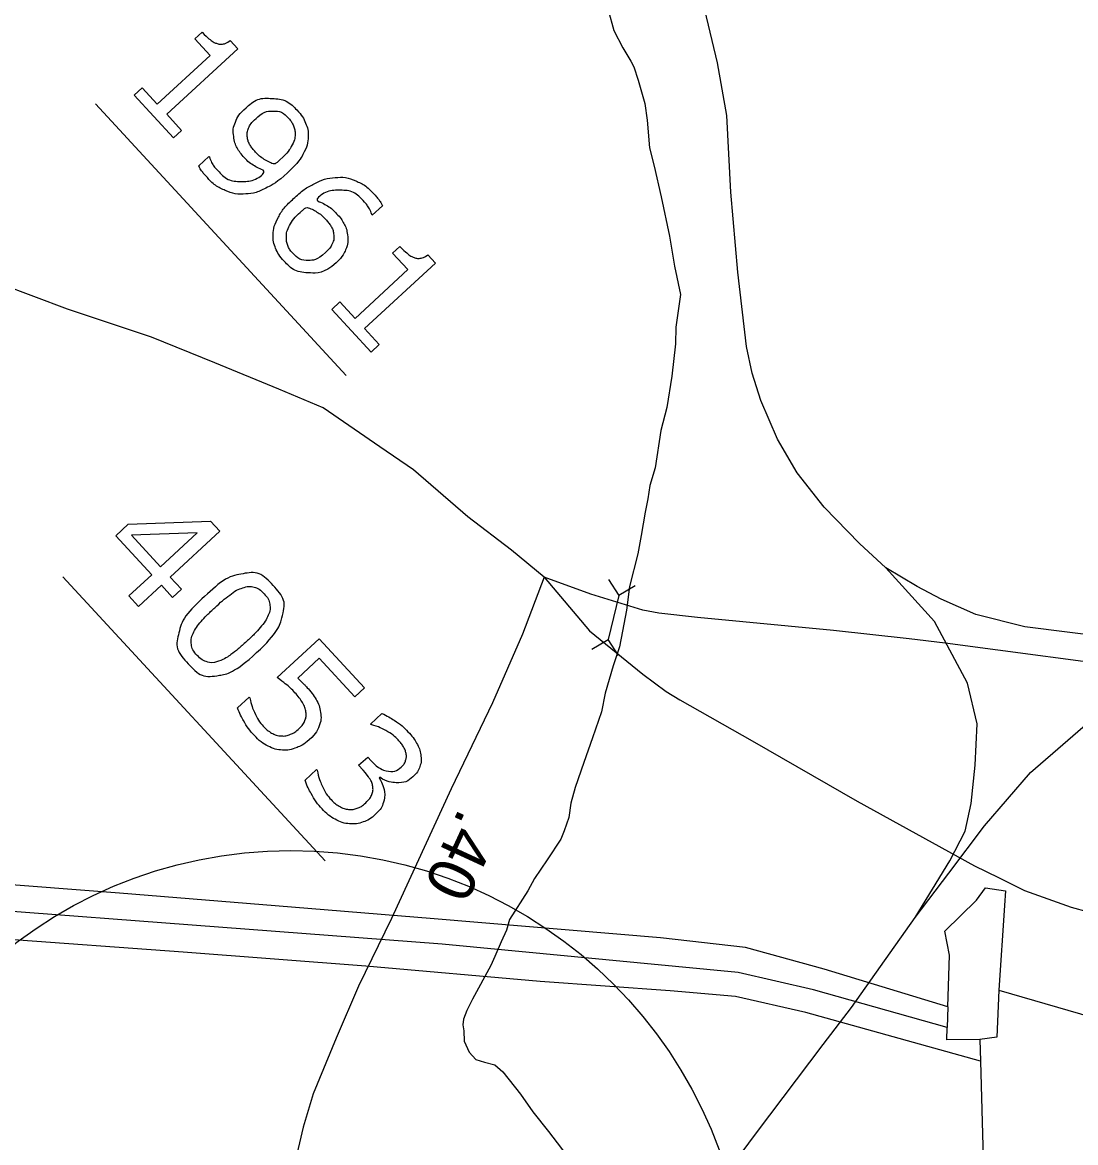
# Model space of a CAD drawing. Extents: x 1695041 to 1706254, y 786537 to 798223.
# Drawn here: x 1703171.6 to 1703301.4, y 796996.4 to 797134.4 of the extents above; entities that cross this region are included whole.
import ezdxf

# ---------------------------------------------------------------- set-up
doc = ezdxf.new("R2010")
doc.units = 0
for name, color, linetype in [('Default', 7, 'Continuous'), ('Old_Level_13', 7, 'Continuous'), ('Old_Level_30', 7, 'Continuous'), ('Old_Level_32', 7, 'Continuous')]:
    doc.layers.add(name, color=color, linetype=linetype)

msp = doc.modelspace()

# ---------------------------------------------------------------- linework, layer by layer
at = {"layer": 'Default'}
for p, q in [((1703180.62, 797124.38), (1703211.51, 797090.92)), ((1703176.62, 797066.11), (1703208.93, 797031.11)), ((1703243.85, 797065.77), (1703245.13, 797063.81)), ((1703247.16, 797064.98), (1703245.13, 797063.81)), ((1703245.13, 797063.81), (1703243.83, 797058.37)), ((1703241.8, 797057.2), (1703243.83, 797058.37)), ((1703245.11, 797056.41), (1703243.83, 797058.37)), ((1703285.68, 797013.13), (1703285.6, 797010.59)), ((1703289.63, 797009.1), (1703289.7, 797006.43))]:
    msp.add_line(p, q, dxfattribs=at)
for points in [[(1703190.25, 797120.18), (1703185.4, 797125.44), (1703186.39, 797126.35), (1703188.25, 797124.33), (1703194.76, 797130.34), (1703192.9, 797132.36), (1703193.78, 797133.18)], [(1703197.23, 797132.16), (1703198.16, 797131.15), (1703189.41, 797123.08), (1703191.24, 797121.1), (1703190.25, 797120.18)], [(1703193.36, 797116.74), (1703194.61, 797117.89), (1703194.67, 797117.83)], [(1703216, 797111.82), (1703214.75, 797110.67), (1703214.69, 797110.73)], [(1703214.61, 797093.79), (1703209.76, 797099.04), (1703210.75, 797099.96), (1703212.62, 797097.94), (1703219.12, 797103.94), (1703217.26, 797105.96), (1703218.15, 797106.78)], [(1703221.59, 797105.77), (1703222.52, 797104.76), (1703213.77, 797096.68), (1703215.6, 797094.7), (1703214.61, 797093.79)], [(1703190.14, 797063.57), (1703188.76, 797065.06), (1703185.94, 797062.45), (1703184.75, 797063.75), (1703187.57, 797066.36), (1703183.13, 797071.16), (1703184.68, 797072.59), (1703194.82, 797072.95), (1703195.97, 797071.71), (1703189.84, 797066.06), (1703191.22, 797064.57), (1703190.14, 797063.57)], [(1703188.65, 797067.35), (1703193.18, 797071.53), (1703185.06, 797071.24), (1703188.65, 797067.35)], [(1703321.31, 797061.94), (1703315.69, 797059.63), (1703313.49, 797058.77), (1703310.57, 797058.37), (1703306.6, 797058.49), (1703295.15, 797059.93), (1703289.13, 797061.46), (1703284.84, 797063.34), (1703281.91, 797064.92), (1703278.04, 797067.22)], [(1703203.04, 797053.69), (1703208.21, 797058.45), (1703213.78, 797052.42), (1703212.6, 797051.33), (1703208.22, 797056.07), (1703205.56, 797053.61)], [(1703285.68, 797013.13), (1703270.43, 797017.78), (1703260.74, 797020.43), (1703250.27, 797021.64), (1703222.38, 797023.95), (1703204.79, 797025.42), (1703183.61, 797027.12), (1703167.05, 797028.4), (1703150.24, 797029.69), (1703133.54, 797030.98), (1703124.57, 797031.78), (1703115.7, 797032.57), (1703115.06, 797037.11), (1703118.33, 797044.24), (1703122.27, 797051.58)], [(1703198.15, 797049.98), (1703199.57, 797051.29), (1703199.66, 797051.19)], [(1703285.6, 797010.59), (1703269.14, 797015.21), (1703259.82, 797017.34), (1703223.36, 797020.86), (1703137.92, 797027.32), (1703108.37, 797031.02), (1703096.16, 797034.26), (1703081.92, 797034.91), (1703062.04, 797036.28), (1703040.38, 797037.67), (1703020.02, 797038.85), (1703002.94, 797039.89), (1702982.67, 797041.42), (1702965.31, 797042.47), (1702957.75, 797042.96), (1702953.78, 797043.59), (1702935.24, 797047.06), (1702923.39, 797049.63), (1702900.08, 797048.94)], [(1703214.57, 797047.9), (1703214.51, 797047.97), (1703215.91, 797049.27)], [(1703289.7, 797006.43), (1703268.17, 797012.44), (1703259.5, 797014.41), (1703251.47, 797015.1), (1703235.43, 797016.24), (1703213.94, 797018.14), (1703191.44, 797019.88), (1703168.84, 797021.51), (1703144.25, 797023.35), (1703122.49, 797025.14), (1703108.81, 797026.43), (1703095.3, 797030.24), (1703081.37, 797031.4), (1703060.9, 797032.87), (1703035.99, 797034.53), (1703015.51, 797035.99), (1702993.46, 797037.4), (1702976.12, 797038.31), (1702961.7, 797039.29), (1702953.95, 797040.12), (1702935.07, 797043.53), (1702923.94, 797045.61), (1702903.01, 797045.39)], [(1703213.62, 797042.27), (1703213.06, 797042.88), (1703214.18, 797043.9), (1703214.61, 797043.43)], [(1703206.46, 797041.07), (1703207.86, 797042.37), (1703207.96, 797042.27)], [(1703215.69, 797041.41), (1703215.6, 797041.33)], [(1703285.68, 797013.13), (1703285.86, 797019.5), (1703285.3, 797022.44), (1703289.2, 797026.27), (1703290.32, 797027.78), (1703292.79, 797027.4), (1703292.65, 797025.63), (1703291.97, 797015.19)], [(1703291.97, 797015.19), (1703291.73, 797009.38), (1703289.63, 797009.1)], [(1703291.97, 797015.19), (1703324.69, 797005.69), (1703340.9, 797002.01), (1703346.94, 797000.11), (1703357.14, 796996.22), (1703368.85, 796991.59), (1703392.4, 796995.22), (1703415.7, 797000.36), (1703437.39, 797006.05), (1703475.08, 797015.18), (1703510.21, 797012.82), (1703534.98, 797011.35), (1703569.35, 797009.42), (1703597.22, 797007.38), (1703614.23, 797006.26), (1703657.83, 797003.31), (1703684.12, 797001.47)], [(1703289.63, 797009.1), (1703285.56, 797009.05), (1703285.6, 797010.59)], [(1703289.7, 797006.43), (1703290.17, 796989.97), (1703290.72, 796977.07), (1703307.24, 796958.38), (1703315.35, 796958.33), (1703339.23, 796958.68), (1703356.95, 796960.92), (1703365.05, 796961.98), (1703390.1, 796965.72), (1703395.31, 796966.42), (1703414.85, 796967.32), (1703433.69, 796950.61)]]:
    msp.add_lwpolyline(points, dxfattribs=at)
msp.add_circle((1703204.73, 796976.2), 56.19, dxfattribs=at)
for points in [[(1703193.78, 797133.18), (1703194.16, 797132.77), (1703194.66, 797132.36), (1703195.17, 797131.95), (1703195.52, 797131.83), (1703195.96, 797131.68), (1703196.37, 797131.74), (1703196.78, 797131.8), (1703197.23, 797132.16)], [(1703194.67, 797117.83), (1703194.74, 797117.55), (1703194.97, 797117.12), (1703195.2, 797116.69), (1703195.59, 797116.27), (1703196.92, 797114.83), (1703198.54, 797114.81), (1703200.16, 797114.79), (1703201.8, 797116.06), (1703200.87, 797116.33), (1703200.22, 797116.72), (1703199.57, 797117.11), (1703198.99, 797117.74), (1703198.44, 797118.34), (1703198.11, 797118.93), (1703197.78, 797119.53), (1703197.67, 797120.33), (1703197.54, 797121.27), (1703197.88, 797122.12), (1703198.23, 797122.98), (1703199.08, 797123.77), (1703200.57, 797125.14), (1703202.41, 797125.03), (1703204.24, 797124.91), (1703205.54, 797123.5), (1703206.19, 797122.8), (1703206.53, 797122), (1703206.86, 797121.2), (1703206.84, 797120.34), (1703206.81, 797119.29), (1703206.24, 797118.2), (1703205.66, 797117.12), (1703204.31, 797115.87)], [(1703203.37, 797117.46), (1703204.38, 797118.39), (1703204.8, 797119.16), (1703205.23, 797119.94), (1703205.23, 797120.62), (1703205.24, 797121.19), (1703205.04, 797121.66), (1703204.84, 797122.13), (1703204.47, 797122.54), (1703203.6, 797123.48), (1703202.51, 797123.48), (1703201.42, 797123.48), (1703200.36, 797122.5), (1703199.74, 797121.93), (1703199.51, 797121.39), (1703199.28, 797120.85), (1703199.37, 797120.17), (1703199.44, 797119.69), (1703199.7, 797119.27), (1703199.95, 797118.86), (1703200.35, 797118.43), (1703200.82, 797117.92), (1703201.44, 797117.53), (1703202.06, 797117.13), (1703202.74, 797116.92), (1703202.88, 797117.04), (1703203.02, 797117.15), (1703203.16, 797117.26), (1703203.37, 797117.46)], [(1703204.31, 797115.87), (1703203.04, 797114.7), (1703201.73, 797114.03), (1703200.43, 797113.36), (1703199.15, 797113.27), (1703197.86, 797113.18), (1703196.63, 797113.7), (1703195.4, 797114.22), (1703194.29, 797115.42), (1703193.98, 797115.76), (1703193.73, 797116.1), (1703193.49, 797116.43), (1703193.36, 797116.74)], [(1703210.28, 797104.79), (1703208.8, 797103.43), (1703206.96, 797103.54), (1703205.13, 797103.65), (1703203.82, 797105.06), (1703203.16, 797105.78), (1703202.84, 797106.57), (1703202.52, 797107.36), (1703202.54, 797108.22), (1703202.57, 797109.28), (1703203.18, 797110.4), (1703203.79, 797111.53), (1703205.05, 797112.69), (1703206.34, 797113.89), (1703207.6, 797114.53), (1703208.85, 797115.17), (1703210.19, 797115.28), (1703211.45, 797115.39), (1703212.71, 797114.87), (1703213.96, 797114.34), (1703215.07, 797113.14), (1703215.43, 797112.75), (1703215.63, 797112.46), (1703215.84, 797112.17), (1703216, 797111.82)], [(1703214.69, 797110.73), (1703214.62, 797111.01), (1703214.37, 797111.46), (1703214.12, 797111.91), (1703213.77, 797112.29), (1703212.47, 797113.69), (1703210.83, 797113.72), (1703209.18, 797113.74), (1703207.56, 797112.5), (1703208.4, 797112.26), (1703209.06, 797111.89), (1703209.73, 797111.52), (1703210.37, 797110.82), (1703210.94, 797110.2), (1703211.26, 797109.62), (1703211.58, 797109.05), (1703211.69, 797108.23), (1703211.82, 797107.29), (1703211.49, 797106.44), (1703211.15, 797105.59), (1703210.28, 797104.79)], [(1703209, 797106.06), (1703209.61, 797106.62), (1703209.84, 797107.17), (1703210.07, 797107.71), (1703209.98, 797108.39), (1703209.92, 797108.89), (1703209.65, 797109.31), (1703209.37, 797109.73), (1703209.01, 797110.13), (1703208.5, 797110.69), (1703207.93, 797111.04), (1703207.36, 797111.39), (1703206.62, 797111.64), (1703206.47, 797111.52), (1703206.33, 797111.41), (1703206.19, 797111.29), (1703205.99, 797111.1), (1703204.96, 797110.16), (1703204.56, 797109.39), (1703204.16, 797108.63), (1703204.16, 797107.94), (1703204.15, 797107.38), (1703204.33, 797106.91), (1703204.52, 797106.44), (1703204.9, 797106.03), (1703205.77, 797105.08), (1703206.85, 797105.08), (1703207.92, 797105.07), (1703209, 797106.06)], [(1703218.15, 797106.78), (1703218.53, 797106.37), (1703219.03, 797105.97), (1703219.53, 797105.56), (1703219.88, 797105.44), (1703220.32, 797105.29), (1703220.73, 797105.35), (1703221.14, 797105.41), (1703221.59, 797105.77)], [(1703200.5, 797056.76), (1703197.79, 797054.26), (1703195.75, 797053.94), (1703193.71, 797053.62), (1703192.06, 797055.39), (1703190.4, 797057.2), (1703190.91, 797059.21), (1703191.43, 797061.23), (1703194.09, 797063.68), (1703196.76, 797066.15), (1703198.82, 797066.49), (1703200.87, 797066.83), (1703202.52, 797065.04), (1703204.18, 797063.24), (1703203.65, 797061.21), (1703203.12, 797059.18), (1703200.5, 797056.76)], [(1703195.8, 797055.7), (1703196.57, 797055.97), (1703197.38, 797056.57), (1703198.2, 797057.17), (1703199.24, 797058.12), (1703200.26, 797059.07), (1703200.94, 797059.85), (1703201.62, 797060.63), (1703201.92, 797061.36), (1703202.22, 797062.08), (1703202.11, 797062.73), (1703202, 797063.38), (1703201.41, 797064.01), (1703200.82, 797064.65), (1703200.18, 797064.82), (1703199.53, 797064.99), (1703198.78, 797064.74), (1703198.06, 797064.51), (1703197.18, 797063.85), (1703196.3, 797063.2), (1703195.35, 797062.31), (1703194.3, 797061.34), (1703193.66, 797060.61), (1703193.02, 797059.88), (1703192.68, 797059.13), (1703192.36, 797058.42), (1703192.46, 797057.76), (1703192.56, 797057.09), (1703193.18, 797056.42), (1703193.76, 797055.79), (1703194.41, 797055.61), (1703195.06, 797055.44), (1703195.8, 797055.7)], [(1703199.66, 797051.19), (1703199.82, 797050.32), (1703200.25, 797049.35), (1703200.69, 797048.38), (1703201.35, 797047.67), (1703201.79, 797047.19), (1703202.34, 797046.86), (1703202.89, 797046.54), (1703203.55, 797046.5), (1703204.11, 797046.47), (1703204.66, 797046.7), (1703205.2, 797046.92), (1703205.74, 797047.41), (1703206.26, 797047.89), (1703206.45, 797048.4), (1703206.64, 797048.91), (1703206.57, 797049.42), (1703206.5, 797050.01), (1703206.14, 797050.61), (1703205.78, 797051.21), (1703205.21, 797051.83), (1703204.67, 797052.42), (1703204.08, 797052.89), (1703203.49, 797053.36), (1703203.04, 797053.69)], [(1703205.56, 797053.61), (1703205.85, 797053.35), (1703206.14, 797053.06), (1703206.44, 797052.77), (1703206.64, 797052.54), (1703207.4, 797051.73), (1703207.82, 797050.99), (1703208.25, 797050.25), (1703208.37, 797049.41), (1703208.5, 797048.53), (1703208.19, 797047.69), (1703207.87, 797046.85), (1703206.99, 797046.04)], [(1703206.99, 797046.04), (1703206.29, 797045.39), (1703205.41, 797045.06), (1703204.54, 797044.72), (1703203.69, 797044.76), (1703202.77, 797044.81), (1703201.9, 797045.25), (1703201.03, 797045.68), (1703200.21, 797046.57), (1703199.45, 797047.39), (1703198.92, 797048.31), (1703198.39, 797049.23), (1703198.15, 797049.98)], [(1703215.91, 797049.27), (1703216.59, 797049), (1703217.52, 797048.39), (1703218.46, 797047.77), (1703219.15, 797047.02), (1703219.83, 797046.29), (1703220.21, 797045.6), (1703220.59, 797044.92), (1703220.71, 797044.2), (1703220.84, 797043.41), (1703220.61, 797042.74), (1703220.38, 797042.07), (1703219.77, 797041.5), (1703218.93, 797040.73), (1703217.77, 797040.74), (1703216.6, 797040.76), (1703215.69, 797041.41)], [(1703214.61, 797043.43), (1703215.56, 797042.41), (1703216.55, 797042.19), (1703217.54, 797041.98), (1703218.37, 797042.74), (1703218.73, 797043.07), (1703218.86, 797043.48), (1703218.99, 797043.89), (1703218.91, 797044.33), (1703218.82, 797044.78), (1703218.58, 797045.17), (1703218.34, 797045.57), (1703217.96, 797045.98), (1703217.37, 797046.62), (1703216.47, 797047.13), (1703215.58, 797047.64), (1703214.57, 797047.9)], [(1703207.96, 797042.27), (1703208.11, 797041.34), (1703208.58, 797040.34), (1703209.04, 797039.33), (1703209.71, 797038.61), (1703210.1, 797038.19), (1703210.68, 797037.84), (1703211.27, 797037.49), (1703211.82, 797037.45), (1703212.4, 797037.41), (1703212.9, 797037.59), (1703213.4, 797037.77), (1703213.94, 797038.28), (1703214.49, 797038.78), (1703214.68, 797039.27), (1703214.88, 797039.77), (1703214.8, 797040.27), (1703214.73, 797040.76), (1703214.41, 797041.27), (1703214.09, 797041.77), (1703213.62, 797042.27)], [(1703216.28, 797039.27), (1703216.29, 797038.68), (1703216.05, 797038.07), (1703215.8, 797037.46), (1703215.11, 797036.82), (1703214.42, 797036.18), (1703213.61, 797035.9), (1703212.81, 797035.62), (1703211.97, 797035.68), (1703211.03, 797035.75), (1703210.18, 797036.23), (1703209.32, 797036.7), (1703208.57, 797037.52), (1703207.8, 797038.35), (1703207.25, 797039.34), (1703206.7, 797040.33), (1703206.46, 797041.07)], [(1703215.6, 797041.33), (1703215.84, 797040.95), (1703216.06, 797040.38), (1703216.27, 797039.8), (1703216.28, 797039.27)]]:
    msp.add_open_spline(points, degree=3, dxfattribs=at)
at = {"layer": 'Old_Level_13'}
for points in [[(1703278.04, 797067.22), (1703274.8, 797070.22), (1703270.43, 797074.68), (1703267.09, 797078.91), (1703264.67, 797083.07), (1703262.61, 797087.81), (1703261.56, 797091.18), (1703260.88, 797094.49), (1703259.8, 797103.64), (1703258.93, 797113.49), (1703258.45, 797122.93), (1703257.31, 797129.4), (1703255.71, 797135.94)], [(1703281.63, 797024.14), (1703285.92, 797031.1), (1703287.79, 797034.77), (1703288.57, 797038.18), (1703289.04, 797042.88), (1703289.28, 797047.99), (1703288.08, 797053), (1703284.05, 797060.59), (1703278.04, 797067.22)], [(1703281.63, 797024.14), (1703285.78, 797029.59), (1703290.2, 797035.41), (1703295.86, 797041.99), (1703304.43, 797049.44), (1703311.79, 797055.55), (1703321.31, 797061.94)], [(1703171.23, 796919.07), (1703180.72, 796925.38), (1703193.26, 796933.69), (1703207.33, 796943), (1703214.53, 796947.8), (1703220.58, 796951.92), (1703224.68, 796955.01), (1703228.4, 796957.58), (1703231, 796959.8), (1703232.58, 796961.14), (1703236.05, 796964.51), (1703236.76, 796965.18), (1703237.53, 796965.99), (1703242.05, 796971.1), (1703244.26, 796974.19), (1703246.44, 796976.87), (1703250.44, 796982.17), (1703255.73, 796989.04), (1703262.11, 796997.6), (1703270.32, 797008.5), (1703273.81, 797013.06), (1703277.38, 797018.09), (1703281.63, 797024.14)]]:
    msp.add_lwpolyline(points, dxfattribs=at)
at = {"layer": 'Old_Level_30'}
for points in [[(1703243.83, 797135.95), (1703244.51, 797133.4), (1703245.62, 797131.25), (1703246.59, 797129.62), (1703246.98, 797128.94), (1703247.51, 797127.27), (1703248.32, 797124.4), (1703248.63, 797122.37), (1703248.9, 797118.95), (1703249.47, 797116.7), (1703250.35, 797112.93), (1703251.36, 797108.05), (1703252, 797104.39), (1703252.72, 797100.9), (1703252.15, 797096.86), (1703252.11, 797094.79), (1703251.66, 797090.84), (1703251.03, 797086.95), (1703250.31, 797084.12), (1703249.62, 797079.54), (1703248.96, 797077.34), (1703248.7, 797075.69), (1703248.38, 797074.08), (1703247.88, 797071.18), (1703247.46, 797068.94), (1703246.45, 797064.92), (1703246.07, 797062), (1703245.58, 797059.39), (1703245.21, 797057.47), (1703244.44, 797055.13), (1703243.44, 797051.76), (1703243.01, 797049.45), (1703241.88, 797046.25), (1703240.83, 797043.22), (1703239.74, 797040.15), (1703239.2, 797038.21), (1703238.98, 797036.44), (1703238.41, 797034.81), (1703238, 797033.78), (1703236.29, 797031.23), (1703234.74, 797028.92), (1703233.92, 797027.43), (1703231.66, 797023.88), (1703231.27, 797022.58), (1703230.62, 797021.14), (1703229.83, 797019.33), (1703229.36, 797018.23), (1703227.08, 797014.09)], [(1703227.08, 797014.09), (1703226.41, 797012.66), (1703225.99, 797011.6), (1703225.92, 797010.9), (1703226.05, 797010.19), (1703226.09, 797008.9), (1703226.67, 797007.56), (1703227.52, 797006.66), (1703228.59, 797006.32), (1703229.84, 797005.99), (1703230.84, 797005.13), (1703233.03, 797002.37), (1703234.55, 797000.18), (1703236.47, 796997.78), (1703239.27, 796994.11)]]:
    msp.add_lwpolyline(points, dxfattribs=at)
at = {"layer": 'Old_Level_32'}
for points in [[(1703235.91, 797066.04), (1703231.89, 797069.38), (1703226.52, 797073.5), (1703219.83, 797079.27), (1703215.66, 797082.12), (1703208.68, 797086.93), (1703203.22, 797089.23), (1703195.35, 797092.48), (1703187.55, 797095.63), (1703177.18, 797099.09), (1703168.91, 797102.2), (1703162.03, 797105.01), (1703154.31, 797107.64), (1703151.39, 797108.53), (1703144, 797110.73), (1703129.49, 797114.72), (1703124.62, 797116.23), (1703121.95, 797117.03), (1703115.84, 797119.7), (1703113.85, 797120.64), (1703110.13, 797122.75), (1703105.95, 797125.3), (1703101.17, 797128.92), (1703092.31, 797135.56)], [(1703235.91, 797066.04), (1703233.25, 797059.04), (1703229.57, 797050.59), (1703224.48, 797039.97), (1703217.12, 797024), (1703213.06, 797015.66), (1703210.31, 797009.28), (1703207.45, 797002.41), (1703206.25, 796998.31), (1703205.32, 796994.46), (1703204.85, 796992.05)], [(1703360.37, 797050.96), (1703358.3, 797051.03), (1703347.02, 797051.54), (1703333.96, 797052.06), (1703325.52, 797052.49), (1703310.67, 797054.58), (1703285.33, 797057.94), (1703280.89, 797058.46), (1703271.59, 797059.5), (1703254.83, 797061.07), (1703250.08, 797061.63), (1703248.08, 797062.01), (1703241.69, 797063.98), (1703235.91, 797066.04)], [(1703235.91, 797066.04), (1703241.51, 797059.46), (1703248.07, 797054.12), (1703250.98, 797051.99), (1703252.65, 797050.95), (1703261.55, 797045.89), (1703274.5, 797038.47), (1703288.97, 797030.5), (1703291.93, 797029.05), (1703295.11, 797027.48), (1703300.86, 797025.4), (1703302.98, 797024.82), (1703306.79, 797024.22), (1703310.71, 797024.3), (1703315.18, 797024.6), (1703321.45, 797025.43), (1703326.34, 797026.21), (1703332.98, 797027.1), (1703339.58, 797028.17), (1703344.36, 797028.55), (1703349.26, 797029.17), (1703355.63, 797029.05), (1703360.87, 797028.8)]]:
    msp.add_lwpolyline(points, dxfattribs=at)

# ---------------------------------------------------------------- texts
at = {"layer": 'Default'}
msp.add_text('.40', height=5.775, rotation=245.2301, dxfattribs=at).set_placement((1703225.52, 797037.79))

doc.saveas('drawing.dxf')
